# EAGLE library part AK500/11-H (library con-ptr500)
CONNECTOR Aug. 2004 / PTR Meßtechnik: Die Bezeichnung der Serie AK505 wurde geändert. Es handelt sich hierbei um AK500 in horizontaler Ausführung.
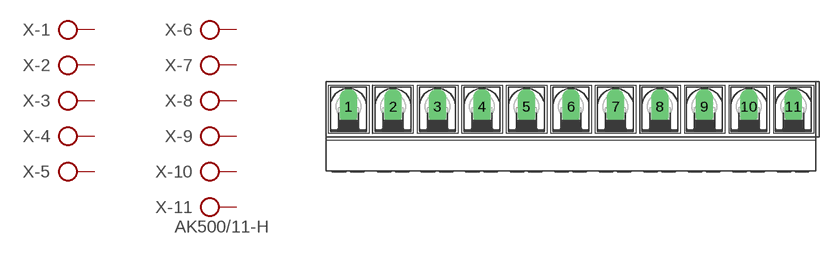
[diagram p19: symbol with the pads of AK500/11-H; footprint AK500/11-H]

Designator prefix X; gates -1=KL -2=KL -3=KL -4=KL -5=KL -6=KL -7=KL -8=KL -9=KL -10=KL -11=KLV

## AK500/11-H (OC_FARNELL: unknown; OC_NEWARK: unknown)  [AK500/11-H]
1  -1:KL  pas
2  -2:KL  pas
3  -3:KL  pas
4  -4:KL  pas
5  -5:KL  pas
6  -6:KL  pas
7  -7:KL  pas
8  -8:KL  pas
9  -9:KL  pas
10  -10:KL  pas
11  -11:KL  pas

## Footprint AK500/11-H (pad centres in mm)
CONNECTOR Aug. 2004 / PTR Meßtechnik: Die Bezeichnung der Serie AK505 wurde geändert. Es handelt sich hierbei um AK500 in horizontaler Ausführung.
drill 1.321 long: 1 -25.019,0; 2 -20.015,0; 3 -15.011,0; 4 -10.008,0; 5 -5.004,0; 6 0,0; 7 5.004,0; 8 10.008,0; 9 15.011,0; 10 20.015,0; 11 25.019,0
